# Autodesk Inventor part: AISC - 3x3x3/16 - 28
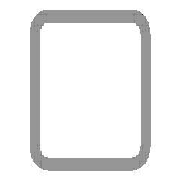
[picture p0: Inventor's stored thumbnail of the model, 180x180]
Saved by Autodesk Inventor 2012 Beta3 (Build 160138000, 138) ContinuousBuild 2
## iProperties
IsCustomPart: 1
_CCFamilyMember: 9
_CCFamilyDisplayName: ANSI AISC (Square) - Tube
_FrameMemberDoc: Frame Member File
_Version: 15.0.0
_GetPNFromCC: 1
Created: 2011-01
Part Number: AISC - 3x3x3/16 - 28
Material: Steel, Mild
Description: Tube
Document SubType Name: Modeling
Standard: ANSI
Designer: Beta-8540w
Standards Organization: ANSI
Language: en-US
Size Designation: 3x3x3/16
Categories: <MemberInstance><Categories><Category DisplayName="Structural Shapes" InternalName="089c4875-fa83-4c05-b084-43b9cc11f5ed" Mnemonic="GRDR"><CategoryParameter Dis
Stock Number: 3x3x3/16
Density: 7.86 g/cm^3
G_L: 28.000 in
G_W: 3.000 in
G_H: 3.000 in
Author: Beta-8540w
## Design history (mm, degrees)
node "Start plane"
node "End plane"
sketch "Sketch"
  geometry: L1 (-38.1, -28.575)-(-38.1, 28.575); L2 (-28.575, 38.1)-(28.575, 38.1); L3 (38.1, 28.575)-(38.1, -28.575); L4 (28.575, -38.1)-(-28.575, -38.1); L5 (-28.575, 33.337)-(28.575, 33.338); L6 (33.338, 28.575)-(33.338, -28.575); L7 (28.575, -33.337)-(-28.575, -33.338); L8 (-33.338, -28.575)-(-33.338, 28.575); L9 (0, 56.102)-(0, -56.102) reference; L10 (-56.102, 0)-(56.102, 0) reference; A1 r 9.525 centre (-28.575, -28.575) between (-38.1, -28.575) and (-28.575, -38.1); A2 r 9.525 centre (-28.575, 28.575) between (-28.575, 38.1) and (-38.1, 28.575); A3 r 9.525 centre (28.575, 28.575) between (38.1, 28.575) and (28.575, 38.1); A4 r 9.525 centre (28.575, -28.575) between (28.575, -38.1) and (38.1, -28.575); A5 r 4.763 centre (-28.575, 28.575) between (-28.575, 33.337) and (-33.338, 28.575); A6 r 4.763 centre (28.575, 28.575) between (33.338, 28.575) and (28.575, 33.338); A7 r 4.763 centre (28.575, -28.575) between (28.575, -33.337) and (33.338, -28.575); A8 r 4.763 centre (-28.575, -28.575) between (-33.338, -28.575) and (-28.575, -33.338)
  constraints: 16 end point, 16 point on circle, 8 centre point, 8 tangent, 4 parallel, 3 equal radius, 2 perpendicular, 7 other
  dimensions: "d10" = 76.2 distance between parallel lines of L2 L4 (= G_H); "d11" = 76.2 distance between parallel lines of L1 L3 (= G_W); "d12" = 4.7625 distance between parallel lines of L3 L6 (= G_T); "d15" = 38.1 distance between parallel lines of L2 L10 (= 0.5 x d10); "d16" = 38.1 distance between parallel lines of L9 L3 (= 0.5 x d11); "d17" = 9.525 radius of A1 (= G_IR)
extrude "Body" new body sketch "Sketch" stored distance "d3" = 711.2 (= G_L); taper "d4" = 0 deg
node "Driven Length"
  sketch "Sketch3"
    geometry: L1 (0, 0)-(10, 0) reference
    constraints: 2 end point, 1 horizontal
  workplane "Work Plane3"
  sketch "Sketch4"
    geometry: L1 (-2, 0)-(12, 0) reference; L2 (-2, 711.2)-(12, 711.2) reference
    dimensions: "d19" = 711.2 distance between parallel lines of L1 L2 (derived)
body "Solid1"
other parameters: "G_W" = 76.2 [user parameter; used in 1 equation term], "G_H" = 76.2 [user parameter; used in 1 equation term], "G_T" = 4.7625 [user parameter; used in 1 equation term], "G_IR" = 9.525 [user parameter; used in 1 equation term], "G_L" = 711.2 (= d19) [user parameter; used in 1 equation term], "G_OFFSET_START" = 0 [user parameter; used in 1 equation term], "G_OFFSET_END" = 0 [user parameter; used in 1 equation term], "d13" = 0 (computed from G_OFFSET_START), "d14" = 711.2 (= G_OFFSET_END + B_L), "B_L" = 711.2 [user parameter; used in 1 equation term], "d18" = 90 deg
